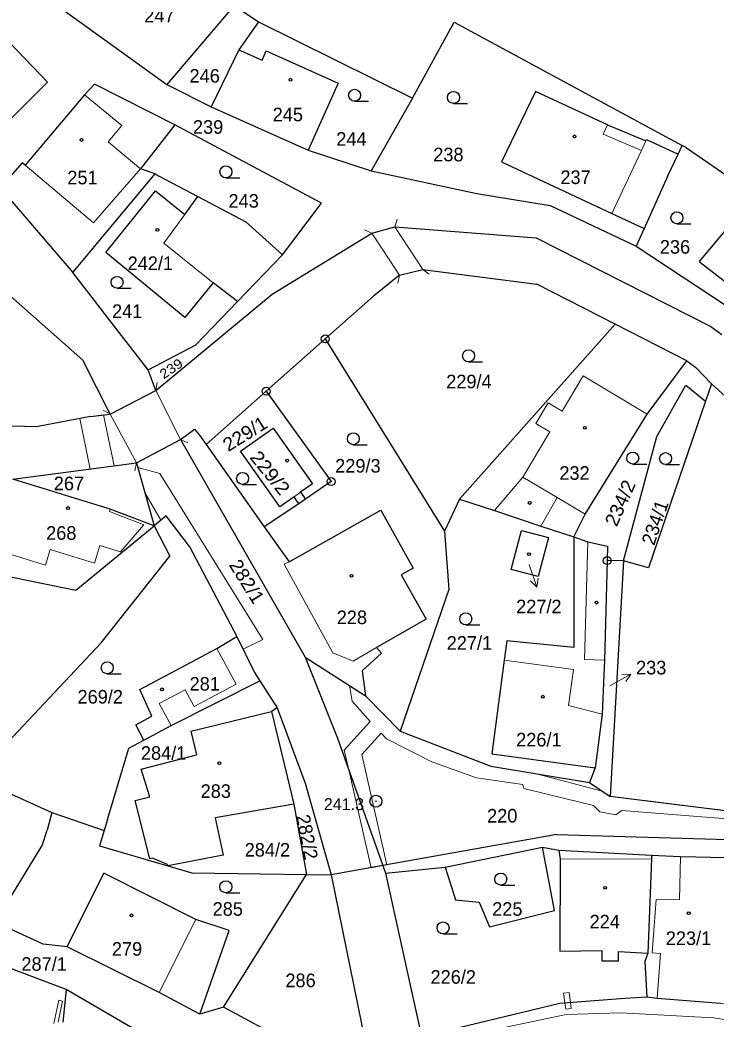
# Model space of a CAD drawing. Extents: x -727701 to -724405, y -960481 to -957284.
# Drawn here: x -726957 to -726869.9, y -958085.7 to -957960.6 of the extents above; entities that cross this region are included whole.
import ezdxf
from ezdxf.enums import TextEntityAlignment as Align

# ---------------------------------------------------------------- set-up
doc = ezdxf.new("R2010")
doc.units = 0
doc.header["$LTSCALE"] = 0.68
for name, color, linetype, lineweight in [('1', 7, 'Continuous', 25), ('13', 7, 'Continuous', 13), ('3', 7, 'Continuous', 25), ('4', 7, 'Continuous', 13), ('5', 7, 'Continuous', 25), ('7', 7, 'Continuous', 13), ('8', 7, 'Continuous', 25)]:
    doc.layers.add(name, color=color, linetype=linetype, lineweight=lineweight)
doc.layers.add('2', color=7, linetype='Continuous')

msp = doc.modelspace()

# ---------------------------------------------------------------- linework, layer by layer
at = {"layer": '1'}
for p, q in [((-726953.44, -957958.01), (-726938.67, -957968.71)), ((-726930.24, -957958.81), (-726938.67, -957968.71)), ((-726930.24, -957958.81), (-726927.19, -957960.86)), ((-726927.19, -957960.86), (-726929.63, -957964.35)), ((-726927.19, -957960.86), (-726907.91, -957970.41)), ((-726907.91, -957970.41), (-726902.67, -957960.91)), ((-726902.67, -957960.91), (-726874.13, -957976.34)), ((-726953.58, -957968.43), (-726959.21, -957962.52)), ((-726929.63, -957964.35), (-726933.08, -957971.5)), ((-726929.63, -957964.35), (-726926.73, -957965.68)), ((-726926.73, -957965.68), (-726926.2, -957964.49)), ((-726926.2, -957964.49), (-726917.2, -957968.53)), ((-726961.28, -957976.08), (-726953.58, -957968.43)), ((-726947.71, -957968.68), (-726948.94, -957969.99)), ((-726937.65, -957973.76), (-726947.71, -957968.68)), ((-726938.67, -957968.71), (-726933.08, -957971.5)), ((-726917.2, -957968.53), (-726920.97, -957976.93)), ((-726892.48, -957969.59), (-726896.75, -957978.37)), ((-726883.48, -957973.77), (-726892.48, -957969.59)), ((-726948.94, -957969.99), (-726956.37, -957978.82)), ((-726907.91, -957970.41), (-726913.09, -957979.52)), ((-726933.08, -957971.5), (-726920.97, -957976.93)), ((-726937.65, -957973.76), (-726941.96, -957979.27)), ((-726919.3, -957983.55), (-726937.65, -957973.76)), ((-726883.48, -957973.77), (-726878.67, -957975.76)), ((-726878.67, -957975.76), (-726878.59, -957975.58)), ((-726878.59, -957975.58), (-726874.65, -957977.42)), ((-726920.97, -957976.93), (-726913.09, -957979.52)), ((-726874.65, -957977.42), (-726874.13, -957976.34)), ((-726873.6, -957976.62), (-726874.13, -957976.34)), ((-726873.6, -957976.62), (-726865.05, -957982.52)), ((-726896.75, -957978.37), (-726882.93, -957984.84)), ((-726875.97, -957980.23), (-726874.65, -957977.42)), ((-726956.74, -957978.5), (-726959.51, -957981.63)), ((-726956.37, -957978.82), (-726956.74, -957978.5)), ((-726940.09, -957979.89), (-726941.96, -957979.27)), ((-726913.09, -957979.52), (-726899.85, -957982.34)), ((-726950.42, -957992.25), (-726940.09, -957979.89)), ((-726940.09, -957979.89), (-726939.68, -957980.12)), ((-726939.68, -957980.12), (-726934.78, -957982.72)), ((-726875.97, -957980.23), (-726878.91, -957986.72)), ((-726959.51, -957981.63), (-726950.42, -957992.25)), ((-726946.3, -957989.75), (-726940.08, -957982.03)), ((-726940.08, -957982.03), (-726936.41, -957984.96)), ((-726936.41, -957984.96), (-726934.78, -957982.72)), ((-726934.78, -957982.72), (-726928.78, -957985.91)), ((-726899.85, -957982.34), (-726890.68, -957983.85)), ((-726865.05, -957982.52), (-726871.99, -957990.85)), ((-726924.16, -957990.02), (-726919.3, -957983.55)), ((-726890.68, -957983.85), (-726879.91, -957988.93)), ((-726928.78, -957985.91), (-726924.16, -957990.02)), ((-726882.93, -957984.84), (-726878.91, -957986.72)), ((-726912.99, -957987.33), (-726910.11, -957986.51)), ((-726910.11, -957986.51), (-726892.42, -957987.88)), ((-726878.91, -957986.72), (-726879.91, -957988.93)), ((-726925.45, -957994.96), (-726912.99, -957987.33)), ((-726892.42, -957987.88), (-726870.57, -957999.01)), ((-726879.91, -957988.93), (-726868.24, -957996.62)), ((-726936.4, -957997.86), (-726946.3, -957989.75)), ((-726924.16, -957990.02), (-726929.81, -957995.87)), ((-726871.99, -957990.85), (-726867, -957994.75)), ((-726909.52, -957992.59), (-726906.62, -957991.85)), ((-726906.62, -957991.85), (-726892.35, -957993.68)), ((-726947.01, -957996.65), (-726950.42, -957992.25)), ((-726909.52, -957992.59), (-726912.77, -957995.19)), ((-726959.34, -957994.18), (-726949.18, -958003.2)), ((-726932.87, -957993.53), (-726936.4, -957997.86)), ((-726929.81, -957995.87), (-726932.87, -957993.53)), ((-726940.02, -958007), (-726925.45, -957994.96)), ((-726935.03, -958001.29), (-726929.81, -957995.87)), ((-726912.77, -957995.19), (-726918.82, -958000.55)), ((-726945.9, -957998.08), (-726947.01, -957996.65)), ((-726941, -958004.44), (-726945.9, -957998.08)), ((-726873.57, -958003.3), (-726882.53, -957998.71)), ((-726870.57, -957999.01), (-726869.17, -957999.98)), ((-726918.82, -958000.55), (-726926.22, -958007.11)), ((-726918.82, -958000.55), (-726903.9, -958024.6)), ((-726941, -958004.44), (-726935.03, -958001.29)), ((-726945.76, -958009.98), (-726949.18, -958003.2)), ((-726878.54, -958009.96), (-726873.57, -958003.3)), ((-726873.57, -958003.3), (-726872.41, -958004.15)), ((-726940.02, -958007), (-726941, -958004.44)), ((-726872.41, -958004.15), (-726870.48, -958006.17)), ((-726945.76, -958009.98), (-726940.02, -958007)), ((-726926.22, -958007.11), (-726933.74, -958013.77)), ((-726877.32, -958012.75), (-726873.67, -958006.36)), ((-726873.67, -958006.36), (-726871.22, -958008.34)), ((-726870.48, -958006.17), (-726871.22, -958008.34)), ((-726870.48, -958006.17), (-726852.89, -958022.19)), ((-726871.22, -958008.34), (-726878.36, -958029.19)), ((-726948.19, -958010.26), (-726954.77, -958011.5)), ((-726948.19, -958010.26), (-726945.76, -958009.98)), ((-726969.55, -958011.22), (-726954.77, -958011.5)), ((-726936.94, -958013.14), (-726935.2, -958011.85)), ((-726935.2, -958011.85), (-726934.56, -958012.61)), ((-726929.43, -958014.62), (-726925.32, -958011.72)), ((-726925.32, -958011.72), (-726920.42, -958018.69)), ((-726942.44, -958016.08), (-726936.94, -958013.14)), ((-726936.94, -958013.14), (-726921.33, -958040.4)), ((-726934.56, -958012.61), (-726933.74, -958013.77)), ((-726881.5, -958028.35), (-726877.32, -958012.75)), ((-726933.74, -958013.77), (-726926.45, -958024.07)), ((-726924.51, -958021.58), (-726929.43, -958014.62)), ((-726957.94, -958018.11), (-726942.44, -958016.08)), ((-726942.44, -958016.08), (-726940.25, -958023.94)), ((-726945.74, -958021.85), (-726957.94, -958018.11)), ((-726920.42, -958018.69), (-726921.92, -958019.75)), ((-726921.92, -958019.75), (-726921.3, -958020.63)), ((-726922.73, -958020.33), (-726924.51, -958021.58)), ((-726922.11, -958021.21), (-726922.73, -958020.33)), ((-726921.3, -958020.63), (-726922.11, -958021.21)), ((-726902, -958020.6), (-726903.9, -958024.6)), ((-726902, -958020.6), (-726897.64, -958022.04)), ((-726940.25, -958023.94), (-726945.74, -958021.85)), ((-726922.11, -958021.21), (-726926.45, -958024.07)), ((-726923.35, -958028.45), (-726911.85, -958022)), ((-726911.85, -958022), (-726907.8, -958029.25)), ((-726897.64, -958022.04), (-726891.83, -958023.97)), ((-726938.75, -958022.71), (-726940.25, -958023.94)), ((-726935.8, -958026.55), (-726938.75, -958022.71)), ((-726950.05, -958032), (-726940.25, -958023.94)), ((-726940.25, -958023.94), (-726938.28, -958027.74)), ((-726926.45, -958024.07), (-726923.35, -958028.45)), ((-726903.9, -958024.6), (-726903.35, -958031.91)), ((-726895.55, -958029.41), (-726894.26, -958024.52)), ((-726891.83, -958023.97), (-726887.72, -958025.33)), ((-726887.72, -958025.33), (-726885.94, -958025.94)), ((-726887.72, -958025.33), (-726887.69, -958039.18)), ((-726885.94, -958025.94), (-726883.47, -958026.5)), ((-726935.8, -958026.55), (-726929.9, -958037.79)), ((-726883.47, -958026.5), (-726883.52, -958028.3)), ((-726946.89, -958038.61), (-726938.28, -958027.74)), ((-726883.52, -958028.3), (-726883.87, -958040.76)), ((-726881.5, -958028.35), (-726883.52, -958028.3)), ((-726881.5, -958028.35), (-726883.16, -958057.83)), ((-726878.36, -958029.19), (-726881.5, -958028.35)), ((-726962.25, -958029.5), (-726950.05, -958032)), ((-726907.8, -958029.25), (-726909.3, -958030.1)), ((-726892.15, -958030.3), (-726895.55, -958029.41)), ((-726909.3, -958030.1), (-726906.19, -958035.62)), ((-726903.35, -958031.91), (-726909.43, -958049.63)), ((-726906.19, -958035.62), (-726912.39, -958039.19)), ((-726932.37, -958039.29), (-726929.9, -958037.79)), ((-726929.9, -958037.79), (-726927.66, -958042.32)), ((-726896.09, -958038.36), (-726896.41, -958040.78)), ((-726887.69, -958039.18), (-726896.09, -958038.36)), ((-726962.73, -958055.45), (-726946.89, -958038.61)), ((-726942.01, -958044.43), (-726932.37, -958039.29)), ((-726912.39, -958039.19), (-726911.76, -958039.89)), ((-726921.33, -958040.4), (-726917.27, -958050.53)), ((-726921.33, -958040.4), (-726913.8, -958045.21)), ((-726911.76, -958039.89), (-726914.19, -958042.08)), ((-726896.41, -958040.78), (-726897.98, -958052.5)), ((-726883.87, -958040.76), (-726884.14, -958047.52)), ((-726914.19, -958042.08), (-726913.8, -958045.21)), ((-726938.12, -958048.95), (-726927.02, -958043.34)), ((-726927.66, -958042.32), (-726927.02, -958043.34)), ((-726940.52, -958047.77), (-726942.01, -958044.43)), ((-726913.8, -958045.21), (-726909.43, -958049.63)), ((-726935.65, -958049.66), (-726925.56, -958047.19)), ((-726925.56, -958047.19), (-726922.74, -958058.77)), ((-726924.83, -958046.75), (-726921.33, -958056.17)), ((-726942.54, -958048.85), (-726940.52, -958047.77)), ((-726884.14, -958047.52), (-726885.04, -958054.23)), ((-726941.52, -958050.76), (-726942.54, -958048.85)), ((-726941.52, -958050.76), (-726938.12, -958048.95)), ((-726935.65, -958049.66), (-726934.92, -958052.63)), ((-726909.43, -958049.63), (-726898.09, -958054.02)), ((-726943.4, -958051.76), (-726941.52, -958050.76)), ((-726917.27, -958050.53), (-726911.62, -958066.48)), ((-726946.06, -958060.69), (-726943.4, -958051.76)), ((-726941.87, -958054.39), (-726934.92, -958052.63)), ((-726897.98, -958052.5), (-726885.04, -958054.23)), ((-726940.78, -958057.87), (-726941.87, -958054.39)), ((-726898.09, -958054.02), (-726885.72, -958056.07)), ((-726885.04, -958054.23), (-726885.72, -958056.07)), ((-726962.73, -958055.45), (-726953.06, -958059.81)), ((-726921.33, -958056.17), (-726918.07, -958067.64)), ((-726885.72, -958056.07), (-726883.16, -958057.83)), ((-726942.6, -958058.32), (-726940.78, -958057.87)), ((-726940.78, -958065.63), (-726942.6, -958058.32)), ((-726866.2, -958059.93), (-726883.16, -958057.83)), ((-726922.74, -958058.77), (-726932.6, -958060.5)), ((-726922.74, -958058.77), (-726921.16, -958067.59)), ((-726953.06, -958059.81), (-726953.61, -958062.04)), ((-726953.06, -958059.81), (-726946.49, -958062.08)), ((-726946.06, -958060.69), (-726946.49, -958062.08)), ((-726932.6, -958060.5), (-726931.6, -958065.16)), ((-726954.24, -958063.98), (-726953.61, -958062.04)), ((-726946.49, -958062.08), (-726947.09, -958064.02)), ((-726889.82, -958062.58), (-726911.62, -958066.48)), ((-726889.82, -958062.58), (-726864.31, -958063.31)), ((-726960.13, -958073.56), (-726954.24, -958063.98)), ((-726947.09, -958064.02), (-726938.54, -958066.52)), ((-726903.8, -958066.69), (-726891.61, -958064.16)), ((-726890.13, -958072.09), (-726891.61, -958064.16)), ((-726891.61, -958064.16), (-726889.56, -958064.56)), ((-726889.56, -958064.56), (-726889.43, -958065.66)), ((-726889.56, -958064.56), (-726877.97, -958065.15)), ((-726940.43, -958065.54), (-726940.78, -958065.63)), ((-726938.58, -958066.32), (-726940.43, -958065.54)), ((-726931.6, -958065.16), (-726938.54, -958066.52)), ((-726889.43, -958065.66), (-726889.46, -958077.17)), ((-726877.98, -958065.61), (-726878.42, -958077.44)), ((-726877.97, -958065.15), (-726877.98, -958065.61)), ((-726877.97, -958065.15), (-726874.35, -958065.33)), ((-726874.35, -958065.33), (-726868.64, -958065.45)), ((-726938.54, -958066.52), (-726938.58, -958066.32)), ((-726938.54, -958066.52), (-726935.53, -958067.4)), ((-726911.62, -958066.48), (-726918.07, -958067.64)), ((-726911.62, -958066.48), (-726911.28, -958067.44)), ((-726911.28, -958067.44), (-726903.8, -958066.69)), ((-726903.8, -958066.69), (-726902.52, -958070.78)), ((-726951.14, -958076.65), (-726946.55, -958067.42)), ((-726935.04, -958073.21), (-726946.55, -958067.42)), ((-726935.53, -958067.4), (-726921.16, -958067.59)), ((-726931.56, -958084.2), (-726921.16, -958067.59)), ((-726921.16, -958067.59), (-726918.07, -958067.64)), ((-726918.07, -958067.64), (-726912.64, -958094.35)), ((-726911.28, -958067.44), (-726906.79, -958087.87)), ((-726902.52, -958070.78), (-726899.55, -958071.06)), ((-726899.55, -958071.06), (-726898.24, -958074.15)), ((-726898.24, -958074.15), (-726890.13, -958072.09)), ((-726930.84, -958074.61), (-726935.04, -958073.21)), ((-726954.11, -958076.32), (-726960.13, -958073.56)), ((-726934.52, -958085.06), (-726930.84, -958074.61)), ((-726951.25, -958082), (-726968.6, -958075.4)), ((-726951.14, -958076.65), (-726954.11, -958076.32)), ((-726939.59, -958082.38), (-726951.14, -958076.65)), ((-726889.46, -958077.17), (-726884.18, -958077.09)), ((-726884.18, -958077.09), (-726884.19, -958078.39)), ((-726882.1, -958078.41), (-726882.09, -958077.21)), ((-726882.09, -958077.21), (-726878.42, -958077.44)), ((-726884.19, -958078.39), (-726882.1, -958078.41)), ((-726878.42, -958077.44), (-726878.83, -958078.47)), ((-726878.83, -958078.47), (-726878.58, -958082.9)), ((-726951.25, -958082), (-726951.68, -958086.07)), ((-726940.93, -958088.01), (-726951.25, -958082)), ((-726934.52, -958085.06), (-726939.59, -958082.38)), ((-726889.47, -958083.69), (-726881.32, -958083.06)), ((-726881.32, -958083.06), (-726878.58, -958082.9)), ((-726878.58, -958082.9), (-726877.28, -958083.06)), ((-726877.28, -958083.06), (-726869.32, -958083.69)), ((-726931.56, -958084.2), (-726934.52, -958085.06)), ((-726912.64, -958094.35), (-726931.56, -958084.2)), ((-726906.79, -958087.87), (-726889.47, -958083.69))]:
    msp.add_line(p, q, dxfattribs=at)
for points in [[(-726902, -958020.6), (-726882.53, -957998.71), (-726892.35, -957993.68)], [(-726926.22, -958007.11), (-726918.09, -958018.41), (-726921.3, -958020.63)], [(-726887.72, -958025.33), (-726886.27, -958022.5), (-726878.54, -958009.96)], [(-726894.26, -958024.52), (-726890.87, -958025.4), (-726892.15, -958030.3)], [(-726927.02, -958043.34), (-726924.83, -958046.75), (-726925.56, -958047.19)]]:
    msp.add_lwpolyline(points, dxfattribs=at)
at = {"layer": '13'}
for points in [[(-726946.57, -958010.07), (-726948.19, -958010.26), (-726949.54, -958010.51), (-726948.23, -958016.84), (-726945.25, -958016.45)], [(-726939.42, -958023.26), (-726938.75, -958022.71), (-726935.8, -958026.55), (-726929.9, -958037.79), (-726929.11, -958039.38), (-726926.64, -958038.16), (-726939.54, -958017.38), (-726942.29, -958016.63), (-726941.38, -958019.88)], [(-726881.32, -958083.06), (-726889.47, -958083.69), (-726906.79, -958087.87), (-726906.11, -958090.11), (-726895.99, -958086.64), (-726888.66, -958085.1), (-726881.81, -958084.9), (-726870.2, -958085.53), (-726866.28, -958086.13), (-726866.49, -958087.81), (-726865.02, -958087.99), (-726864.47, -958087.79), (-726864.2, -958085.58), (-726864.93, -958084.62), (-726865.48, -958084.56), (-726869.32, -958083.69), (-726877.28, -958083.06), (-726878.58, -958082.9)], [(-726888.83, -958083.64), (-726888.13, -958083.59), (-726888.29, -958082.34), (-726888.99, -958082.43)], [(-726888.72, -958084.45), (-726888.02, -958084.36), (-726888.13, -958083.59), (-726888.83, -958083.64)]]:
    msp.add_lwpolyline(points, close=True, dxfattribs=at)
for points in [[(-726864.73, -958060.11), (-726883.16, -958057.83), (-726884.14, -958057.15), (-726892.37, -958054.97), (-726898.09, -958054.02), (-726909.43, -958049.63), (-726913.8, -958045.21), (-726915.77, -958043.95), (-726915.44, -958045.91), (-726913.19, -958048.45), (-726916.43, -958052.01), (-726915.86, -958054.51), (-726913.07, -958066.74), (-726911.62, -958066.48), (-726911.1, -958066.39), (-726914.25, -958052.59), (-726911.82, -958049.91), (-726911.13, -958050.6), (-726905.47, -958053.49), (-726899.87, -958055.49), (-726894.07, -958056.32), (-726893.94, -958056.82), (-726885.22, -958058.95), (-726884.43, -958059.76), (-726882.45, -958060.11), (-726881.7, -958059.57), (-726860.58, -958061.26)], [(-726952.25, -958086.06), (-726951.71, -958083.43), (-726952.19, -958083.33), (-726952.81, -958086.26)]]:
    msp.add_lwpolyline(points, dxfattribs=at)
at = {"layer": '3'}
for p, q in [((-726915.143, -957970.81), (-726913.393, -957970.81)), ((-726902.763, -957971.08), (-726901.013, -957971.08)), ((-726931.253, -957980.39), (-726929.503, -957980.39)), ((-726874.793, -957986.14), (-726873.043, -957986.14)), ((-726944.873, -957994.22), (-726943.123, -957994.22)), ((-726900.883, -958003.42), (-726899.133, -958003.42)), ((-726915.303, -958013.79), (-726913.553, -958013.79)), ((-726880.323, -958016.21), (-726878.573, -958016.21)), ((-726876.213, -958016.28), (-726874.463, -958016.28)), ((-726929.163, -958018.77), (-726927.413, -958018.77)), ((-726901.223, -958036.34), (-726899.473, -958036.34)), ((-726946.113, -958042.47), (-726944.363, -958042.47)), ((-726896.843, -958068.92), (-726895.093, -958068.92)), ((-726931.263, -958069.88), (-726929.513, -958069.88)), ((-726904.073, -958075.02), (-726902.323, -958075.02))]:
    msp.add_line(p, q, dxfattribs=at)
for centre in [(-726915.1429, -957970.0598), (-726902.7629, -957970.3298), (-726931.2529, -957979.6398), (-726874.7929, -957985.3898), (-726944.8729, -957993.4698), (-726900.8829, -958002.6698), (-726915.3029, -958013.0398), (-726880.3229, -958015.4598), (-726876.2129, -958015.5298), (-726929.1629, -958018.0198), (-726901.2229, -958035.5898), (-726946.1129, -958041.7198), (-726931.2629, -958069.1298), (-726896.8429, -958068.1698), (-726904.0729, -958074.2698)]:
    msp.add_circle(centre, 0.75, dxfattribs=at)
at = {"layer": '4'}
for p, q in [((-726948.94, -957969.99), (-726944.3, -957973.85)), ((-726944.3, -957973.85), (-726945.99, -957975.88)), ((-726883.48, -957973.77), (-726884.01, -957974.92)), ((-726945.99, -957975.88), (-726941.96, -957979.27)), ((-726884.01, -957974.92), (-726879.24, -957976.96)), ((-726879.24, -957976.96), (-726878.67, -957975.76)), ((-726879.24, -957976.96), (-726879.91, -957978.39)), ((-726879.91, -957978.39), (-726882.93, -957984.84)), ((-726947.85, -957986.04), (-726956.37, -957978.82)), ((-726941.96, -957979.27), (-726947.85, -957986.04)), ((-726939.03, -957988.55), (-726936.41, -957984.96)), ((-726909.834, -957985.548), (-726910.109, -957986.51)), ((-726913.896, -957986.907), (-726912.99, -957987.329)), ((-726910.11, -957986.51), (-726906.62, -957991.85)), ((-726912.99, -957987.33), (-726909.52, -957992.59)), ((-726932.87, -957993.53), (-726939.03, -957988.55)), ((-726905.811, -957992.438), (-726906.62, -957991.851)), ((-726909.746, -957993.565), (-726909.521, -957992.59)), ((-726889.16, -958009.61), (-726886.52, -958005.19)), ((-726886.52, -958005.19), (-726878.54, -958009.96)), ((-726940.02, -958007), (-726936.94, -958013.14)), ((-726939.846, -958006.015), (-726940.019, -958007)), ((-726946.617, -958009.464), (-726945.76, -958009.979)), ((-726892.46, -958011.14), (-726890.92, -958008.56)), ((-726889.16, -958009.61), (-726890.92, -958008.56)), ((-726945.76, -958009.98), (-726942.44, -958016.08)), ((-726894.09, -958017.86), (-726890.7, -958012.19)), ((-726890.7, -958012.19), (-726892.46, -958011.14)), ((-726936.041, -958013.579), (-726936.94, -958013.141)), ((-726942.666, -958017.055), (-726942.441, -958016.08)), ((-726897.64, -958022.04), (-726894.09, -958017.86)), ((-726889.79, -958020.41), (-726894.09, -958017.86)), ((-726922.73, -958020.33), (-726921.92, -958019.75)), ((-726891.83, -958023.97), (-726889.79, -958020.41)), ((-726886.27, -958022.5), (-726889.79, -958020.41)), ((-726945.74, -958021.85), (-726945.83, -958022.14)), ((-726945.83, -958022.14), (-726941.54, -958023.84)), ((-726941.54, -958023.84), (-726944.43, -958027.21)), ((-726886.38, -958040.69), (-726885.94, -958025.94)), ((-726953.85, -958028.86), (-726960.6, -958026.79)), ((-726953.26, -958026.93), (-726953.85, -958028.86)), ((-726947.72, -958028.63), (-726953.26, -958026.93)), ((-726947.04, -958026.41), (-726947.72, -958028.63)), ((-726944.43, -958027.21), (-726947.04, -958026.41)), ((-726923.98, -958028.74), (-726923.35, -958028.45)), ((-726917.88, -958039.85), (-726923.98, -958028.74)), ((-726932.37, -958039.29), (-726929.98, -958043.76)), ((-726912.39, -958039.19), (-726915.32, -958040.87)), ((-726915.32, -958040.87), (-726917.88, -958039.85)), ((-726896.41, -958040.78), (-726887.75, -958041.94)), ((-726883.87, -958040.76), (-726886.38, -958040.69)), ((-726887.75, -958041.94), (-726888.35, -958046.42)), ((-726936.34, -958044.46), (-726939.59, -958046.19)), ((-726935.22, -958046.56), (-726936.34, -958044.46)), ((-726929.98, -958043.76), (-726935.22, -958046.56)), ((-726939.59, -958046.19), (-726938.12, -958048.95)), ((-726888.35, -958046.42), (-726884.14, -958047.52)), ((-726889.43, -958065.66), (-726877.98, -958065.61)), ((-726874.46, -958070.78), (-726874.35, -958065.33)), ((-726877.38, -958070.72), (-726877.9, -958077.4)), ((-726877.38, -958070.72), (-726874.46, -958070.78)), ((-726935.04, -958073.21), (-726939.59, -958082.38)), ((-726877.9, -958077.4), (-726876.84, -958077.48)), ((-726876.84, -958077.48), (-726877.28, -958083.06))]:
    msp.add_line(p, q, dxfattribs=at)
at = {"layer": '5'}
for centre in [(-726923.1668, -957968.1092), (-726949.3368, -957975.6492), (-726887.6068, -957975.1992), (-726939.8368, -957986.8992), (-726886.3168, -958011.6892), (-726923.5968, -958015.7892), (-726893.2268, -958021.0892), (-726951.0168, -958021.7192), (-726893.3068, -958027.4992), (-726915.5268, -958030.2192), (-726884.8668, -958033.5592), (-726939.2568, -958044.4192), (-726891.5768, -958045.3392), (-726932.0768, -958053.6492), (-726883.7768, -958069.2492), (-726873.3168, -958072.4292), (-726943.0768, -958072.7092)]:
    msp.add_circle(centre, 0.175, dxfattribs=at)
at = {"layer": '7'}
for p, q in [((-726892.323, -958031.617), (-726892.176, -958030.508)), ((-726880.555, -958042.505), (-726881.674, -958042.553))]:
    msp.add_line(p, q, dxfattribs=at)
for points in [[(-726893.3, -958028.78), (-726892.323, -958031.617), (-726893.122, -958030.834)], [(-726883.18, -958043.96), (-726880.555, -958042.505), (-726881.188, -958043.429)]]:
    msp.add_lwpolyline(points, dxfattribs=at)
at = {"layer": '8'}
for centre, radius in [((-726918.82, -958000.5499), 0.5), ((-726918.82, -958000.5499), 0.0303), ((-726926.22, -958007.1099), 0.5), ((-726926.22, -958007.1099), 0.0303), ((-726918.09, -958018.4099), 0.5), ((-726918.09, -958018.4099), 0.0303), ((-726883.52, -958028.2999), 0.5), ((-726883.52, -958028.2999), 0.0303), ((-726912.47, -958058.4198), 0.75), ((-726912.47, -958058.4198), 0.03)]:
    msp.add_circle(centre, radius, dxfattribs=at)

# ---------------------------------------------------------------- texts
at = {"layer": '2'}
for s, p in [('247', (-726941.47, -957960.925)), ('246', (-726935.81, -957968.475)), ('245', (-726925.4, -957973.315)), ('239', (-726935.38, -957974.875)), ('244', (-726917.44, -957976.375)), ('238', (-726905.3, -957978.325)), ('251', (-726951.11, -957981.205)), ('237', (-726889.38, -957981.165)), ('243', (-726930.93, -957984.125)), ('236', (-726876.93, -957989.885)), ('242/1', (-726943.56, -957991.935)), ('241', (-726945.51, -957997.935)), ('232', (-726889.51, -958018.185)), ('267', (-726952.8, -958019.495)), ('268', (-726953.76, -958025.695)), ('228', (-726917.38, -958036.255)), ('233', (-726879.91, -958042.545)), ('281', (-726935.8, -958044.575)), ('269/2', (-726949.83, -958046.195)), ('226/1', (-726894.92, -958051.565)), ('283', (-726934.42, -958058.005)), ('220', (-726898.56, -958061.085)), ('285', (-726932.92, -958072.755)), ('225', (-726897.92, -958072.755)), ('224', (-726885.73, -958074.345)), ('223/1', (-726876.19, -958076.415)), ('279', (-726945.53, -958077.755)), ('226/2', (-726905.64, -958081.265))]:
    msp.add_text(s, height=1.7, dxfattribs=at).set_placement(p)
for s, height, rotation, width, p in [('239', 1.2, 34, 1.15, (-726939.052, -958005.628)), ('229/1', 1.7, 32, 1.05, (-726930.954, -958014.73)), ('229/2', 1.7, 309, 1.1, (-726928.36, -958015.417)), ('282/1', 1.7, 302, 1.05, (-726930.94, -958028.825))]:
    msp.add_text(s, height=height, rotation=rotation, dxfattribs=dict(at, width=width)).set_placement(p)
for s, p in [('229/4', (-726900.83, -958006.735)), ('229/3', (-726914.73, -958017.285)), ('227/2', (-726892.08, -958034.895)), ('227/1', (-726900.77, -958039.455)), ('284/1', (-726939.05, -958053.235)), ('284/2', (-726926.06, -958065.355)), ('287/1', (-726954.01, -958079.645)), ('286', (-726921.909, -958081.695))]:
    msp.add_text(s, height=1.7, dxfattribs=at).set_placement(p, align=Align.CENTER)
at = {"layer": '2', "width": 1.05}
msp.add_text('234/2', height=1.7, rotation=66, dxfattribs=at).set_placement((-726881.1229, -958021.4357), align=Align.CENTER)
at = {"layer": '2'}
for s, rotation, p in [('234/1', 71, (-726877.658, -958026.498)), ('282/2', 281, (-726922.457, -958060.271))]:
    msp.add_text(s, height=1.7, rotation=rotation, dxfattribs=at).set_placement(p)
at = {"layer": '8'}
msp.add_text('241.3', height=1.5, dxfattribs=at).set_placement((-726913.969, -958059.537), align=Align.RIGHT)

doc.saveas('drawing.dxf')
